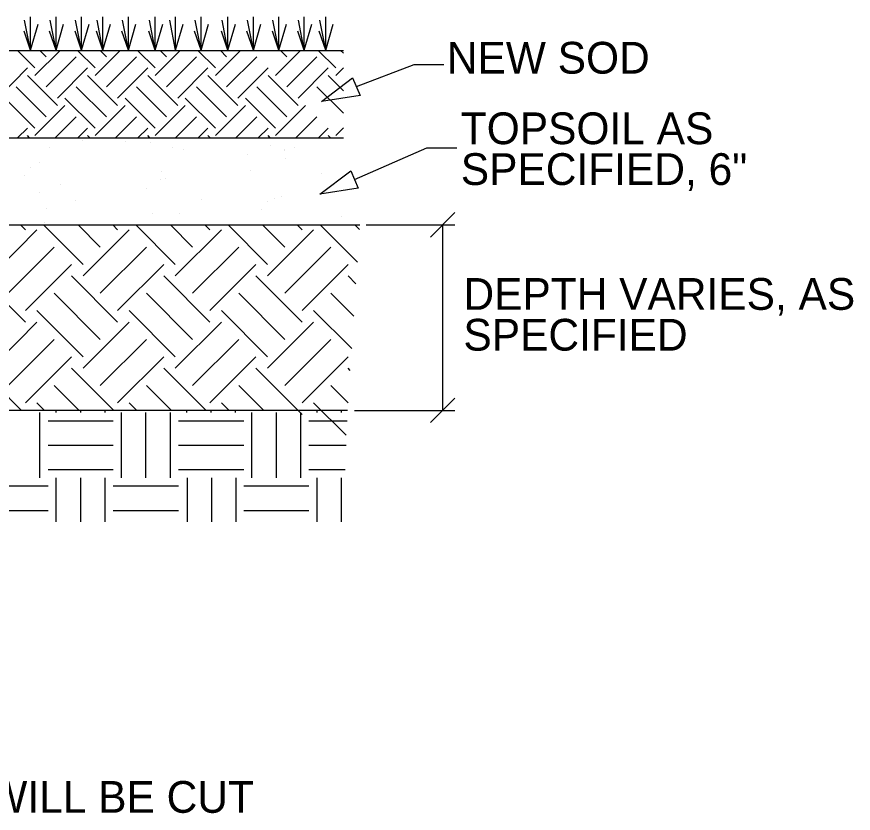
# Model space of a CAD drawing. Extents: x 10146.6 to 10186.7, y 9955.2 to 10001.8.
# Drawn here: x 10168.25 to 10186.68, y 9979.42 to 9996.98 of the extents above; entities that cross this region are included whole.
import ezdxf

# ---------------------------------------------------------------- set-up
doc = ezdxf.new("R2010")
doc.units = 0
for name, color, linetype in [('Default', 7, 'Continuous'), ('G-DETL-OTLN', 7, 'Continuous'), ('G-DETL-PATT', 7, 'Continuous'), ('G-DETL-TEXT', 7, 'Continuous')]:
    doc.layers.add(name, color=color, linetype=linetype)

# ---------------------------------------------------------------- blocks, each defined once
blk = doc.blocks.new('TERARR')
at = {"layer": 'Default'}
blk.add_lwpolyline([(-0.667, 0.167), (0, 0), (-0.667, -0.167)], close=True, dxfattribs=at)

msp = doc.modelspace()

# ---------------------------------------------------------------- linework, layer by layer
at = {"layer": 'Default'}
for p, q in [((10177.904, 9992.66), (10177.363, 9992.119)), ((10175.949, 9992.389), (10177.904, 9992.389)), ((10177.634, 9992.394), (10177.634, 9988.3)), ((10177.904, 9988.571), (10177.363, 9988.03)), ((10175.689, 9988.3), (10177.904, 9988.3))]:
    msp.add_line(p, q, dxfattribs=at)
at = {"layer": 'G-DETL-OTLN'}
for points in [[(10157.311, 9996.235), (10175.448, 9996.235)], [(10157.311, 9994.307), (10175.448, 9994.307)], [(10157.272, 9992.435), (10157.272, 9988.305), (10175.536, 9988.305)], [(10157.434, 9992.388), (10175.807, 9992.388)]]:
    msp.add_lwpolyline(points, dxfattribs=at)
at = {"layer": 'G-DETL-PATT'}
for p, q in [((10168.55, 9996.238), (10168.421, 9996.901)), ((10168.55, 9996.238), (10168.55, 9996.977)), ((10169.112, 9996.238), (10168.983, 9996.901)), ((10169.112, 9996.238), (10169.112, 9996.977)), ((10169.674, 9996.238), (10169.544, 9996.901)), ((10169.674, 9996.238), (10169.674, 9996.977)), ((10170.145, 9996.238), (10170.016, 9996.901)), ((10170.145, 9996.238), (10170.145, 9996.977)), ((10170.707, 9996.238), (10170.577, 9996.901)), ((10170.707, 9996.238), (10170.707, 9996.977)), ((10171.3, 9996.238), (10171.171, 9996.901)), ((10171.3, 9996.238), (10171.3, 9996.977)), ((10171.747, 9996.238), (10171.618, 9996.901)), ((10171.747, 9996.238), (10171.747, 9996.977)), ((10172.309, 9996.238), (10172.18, 9996.901)), ((10172.309, 9996.238), (10172.309, 9996.977)), ((10172.9, 9996.238), (10172.771, 9996.901)), ((10172.9, 9996.238), (10172.9, 9996.977)), ((10173.462, 9996.238), (10173.332, 9996.901)), ((10173.462, 9996.238), (10173.462, 9996.977)), ((10174.024, 9996.238), (10173.894, 9996.901)), ((10174.024, 9996.238), (10174.024, 9996.977)), ((10174.585, 9996.238), (10174.456, 9996.901)), ((10174.585, 9996.238), (10174.585, 9996.977)), ((10175.057, 9996.238), (10174.927, 9996.901)), ((10175.057, 9996.238), (10175.057, 9996.977)), ((10168.55, 9996.238), (10168.409, 9996.657)), ((10168.55, 9996.238), (10168.716, 9996.811)), ((10169.112, 9996.238), (10168.97, 9996.657)), ((10169.112, 9996.238), (10169.278, 9996.811)), ((10169.674, 9996.238), (10169.532, 9996.657)), ((10169.674, 9996.238), (10169.84, 9996.811)), ((10170.145, 9996.238), (10170.003, 9996.657)), ((10170.145, 9996.238), (10170.311, 9996.811)), ((10170.707, 9996.238), (10170.565, 9996.657)), ((10170.707, 9996.238), (10170.873, 9996.811)), ((10171.3, 9996.238), (10171.159, 9996.657)), ((10171.3, 9996.238), (10171.466, 9996.811)), ((10171.747, 9996.238), (10171.913, 9996.811)), ((10172.309, 9996.238), (10172.167, 9996.657)), ((10172.309, 9996.238), (10172.475, 9996.811)), ((10172.9, 9996.238), (10172.758, 9996.657)), ((10172.9, 9996.238), (10173.066, 9996.811)), ((10173.462, 9996.238), (10173.32, 9996.657)), ((10173.462, 9996.238), (10173.628, 9996.811)), ((10174.024, 9996.238), (10173.882, 9996.657)), ((10174.024, 9996.238), (10174.19, 9996.811)), ((10174.585, 9996.238), (10174.444, 9996.657)), ((10174.585, 9996.238), (10174.751, 9996.811)), ((10175.057, 9996.238), (10174.915, 9996.657)), ((10175.057, 9996.238), (10175.223, 9996.811)), ((10168.647, 9995.848), (10168.26, 9996.235)), ((10168.647, 9995.682), (10169.201, 9996.235)), ((10168.896, 9996.096), (10168.757, 9996.235)), ((10168.896, 9995.433), (10169.559, 9996.096)), ((10169.973, 9995.848), (10169.586, 9996.235)), ((10169.973, 9995.682), (10170.526, 9996.235)), ((10170.222, 9996.096), (10170.083, 9996.235)), ((10170.222, 9995.433), (10170.885, 9996.096)), ((10171.299, 9995.848), (10170.911, 9996.235)), ((10171.299, 9995.682), (10171.852, 9996.235)), ((10171.548, 9996.096), (10171.409, 9996.235)), ((10171.548, 9995.433), (10172.211, 9996.096)), ((10172.625, 9995.848), (10172.237, 9996.235)), ((10172.625, 9995.682), (10173.178, 9996.235)), ((10172.873, 9996.096), (10172.734, 9996.235)), ((10172.873, 9995.433), (10173.536, 9996.096)), ((10173.951, 9995.682), (10174.504, 9996.235)), ((10174.199, 9996.096), (10174.06, 9996.235)), ((10174.199, 9995.433), (10174.862, 9996.096)), ((10175.276, 9995.848), (10174.889, 9996.235)), ((10175.448, 9996.173), (10175.386, 9996.235)), ((10167.819, 9995.185), (10168.482, 9995.848)), ((10169.145, 9995.185), (10169.807, 9995.848)), ((10170.47, 9995.185), (10171.133, 9995.848)), ((10171.796, 9995.185), (10172.459, 9995.848)), ((10173.122, 9995.185), (10173.785, 9995.848)), ((10174.448, 9995.185), (10175.111, 9995.848)), ((10175.276, 9995.682), (10175.448, 9995.854)), ((10169.145, 9995.019), (10168.482, 9995.682)), ((10170.47, 9995.019), (10169.807, 9995.682)), ((10171.796, 9995.019), (10171.133, 9995.682)), ((10173.122, 9995.019), (10172.459, 9995.682)), ((10174.448, 9995.019), (10173.785, 9995.682)), ((10175.448, 9995.345), (10175.111, 9995.682)), ((10168.896, 9994.771), (10168.233, 9995.433)), ((10170.222, 9994.771), (10169.559, 9995.433)), ((10171.548, 9994.771), (10170.885, 9995.433)), ((10172.873, 9994.771), (10172.211, 9995.433)), ((10174.199, 9994.771), (10173.536, 9995.433)), ((10175.448, 9994.848), (10174.862, 9995.433)), ((10168.647, 9994.522), (10167.984, 9995.185)), ((10169.973, 9994.522), (10169.31, 9995.185)), ((10171.299, 9994.522), (10170.636, 9995.185)), ((10172.625, 9994.522), (10171.962, 9995.185)), ((10173.951, 9994.522), (10173.288, 9995.185)), ((10168.647, 9994.356), (10169.31, 9995.019)), ((10169.973, 9994.356), (10170.636, 9995.019)), ((10171.299, 9994.356), (10171.962, 9995.019)), ((10172.625, 9994.356), (10173.288, 9995.019)), ((10173.951, 9994.356), (10174.614, 9995.019)), ((10169.095, 9994.307), (10169.559, 9994.771)), ((10170.421, 9994.307), (10170.885, 9994.771)), ((10171.747, 9994.307), (10172.211, 9994.771)), ((10173.072, 9994.307), (10173.536, 9994.771)), ((10174.398, 9994.307), (10174.862, 9994.771)), ((10168.266, 9994.307), (10168.482, 9994.522)), ((10169.592, 9994.307), (10169.807, 9994.522)), ((10170.918, 9994.307), (10171.133, 9994.522)), ((10172.244, 9994.307), (10172.459, 9994.522)), ((10173.57, 9994.307), (10173.785, 9994.522)), ((10174.895, 9994.307), (10175.111, 9994.522)), ((10175.276, 9994.356), (10175.448, 9994.528)), ((10168.531, 9994.307), (10168.482, 9994.356)), ((10169.857, 9994.307), (10169.807, 9994.356)), ((10171.183, 9994.307), (10171.133, 9994.356)), ((10172.509, 9994.307), (10172.459, 9994.356)), ((10173.835, 9994.307), (10173.785, 9994.356)), ((10175.16, 9994.307), (10175.111, 9994.356)), ((10168.975, 9994.096), (10168.975, 9994.096)), ((10169.688, 9994.243), (10169.688, 9994.243)), ((10170.639, 9994.22), (10170.639, 9994.22)), ((10171.191, 9994.209), (10171.191, 9994.209)), ((10171.675, 9994.096), (10171.675, 9994.096)), ((10173.83, 9994.145), (10173.83, 9994.145)), ((10174.375, 9994.096), (10174.375, 9994.096)), ((10171.929, 9994.047), (10171.929, 9994.047)), ((10173.324, 9993.938), (10173.324, 9993.938)), ((10174.138, 9994.056), (10174.138, 9994.056)), ((10174.154, 9994.027), (10174.154, 9994.027)), ((10168.739, 9993.775), (10168.739, 9993.775)), ((10174.171, 9993.851), (10174.171, 9993.851)), ((10168.55, 9993.648), (10168.55, 9993.648)), ((10171.447, 9993.568), (10171.447, 9993.568)), ((10173.403, 9993.584), (10173.403, 9993.584)), ((10174.961, 9993.516), (10174.961, 9993.516)), ((10168.411, 9993.475), (10168.411, 9993.475)), ((10171.413, 9993.399), (10171.413, 9993.399)), ((10171.518, 9993.403), (10171.518, 9993.403)), ((10169.21, 9993.289), (10169.21, 9993.289)), ((10171.096, 9993.193), (10171.096, 9993.193)), ((10168.739, 9993.108), (10168.739, 9993.108)), ((10173.918, 9992.978), (10173.918, 9992.978)), ((10174.086, 9993.023), (10174.086, 9993.023)), ((10169.535, 9992.931), (10169.535, 9992.931)), ((10172.32, 9992.955), (10172.32, 9992.955)), ((10173.782, 9992.91), (10173.782, 9992.91)), ((10168.899, 9992.75), (10168.899, 9992.75)), ((10171.238, 9992.649), (10171.238, 9992.649)), ((10171.83, 9992.636), (10171.83, 9992.636)), ((10173.631, 9992.733), (10173.631, 9992.733)), ((10168.869, 9992.447), (10168.869, 9992.447)), ((10175.408, 9992.563), (10175.408, 9992.563)), ((10167.675, 9991.263), (10168.692, 9992.279)), ((10168.437, 9992.279), (10168.328, 9992.388)), ((10169.708, 9991.517), (10168.837, 9992.388)), ((10170.089, 9991.898), (10169.599, 9992.388)), ((10169.679, 9992.394), (10169.679, 9992.394)), ((10169.708, 9991.263), (10170.724, 9992.279)), ((10170.47, 9992.279), (10170.361, 9992.388)), ((10171.741, 9991.517), (10170.87, 9992.388)), ((10172.122, 9991.898), (10171.632, 9992.388)), ((10171.741, 9991.263), (10172.757, 9992.279)), ((10172.503, 9992.279), (10172.394, 9992.388)), ((10173.774, 9991.517), (10172.903, 9992.388)), ((10174.155, 9991.898), (10173.665, 9992.388)), ((10173.774, 9991.263), (10174.79, 9992.279)), ((10174.536, 9992.279), (10174.427, 9992.388)), ((10175.754, 9991.57), (10174.936, 9992.388)), ((10175.8, 9992.286), (10175.698, 9992.388)), ((10168.056, 9990.881), (10169.073, 9991.898)), ((10170.089, 9990.881), (10171.106, 9991.898)), ((10172.122, 9990.881), (10173.139, 9991.898)), ((10174.155, 9990.881), (10175.172, 9991.898)), ((10168.437, 9990.5), (10169.454, 9991.517)), ((10170.47, 9990.5), (10171.487, 9991.517)), ((10172.503, 9990.5), (10173.52, 9991.517)), ((10174.536, 9990.5), (10175.553, 9991.517)), ((10168.437, 9990.246), (10167.421, 9991.263)), ((10170.47, 9990.246), (10169.454, 9991.263)), ((10172.503, 9990.246), (10171.487, 9991.263)), ((10174.536, 9990.246), (10173.52, 9991.263)), ((10175.723, 9991.093), (10175.553, 9991.263)), ((10170.089, 9989.865), (10169.073, 9990.881)), ((10172.122, 9989.865), (10171.106, 9990.881)), ((10174.155, 9989.865), (10173.139, 9990.881)), ((10175.676, 9990.377), (10175.172, 9990.881)), ((10169.708, 9989.484), (10168.692, 9990.5)), ((10171.741, 9989.484), (10170.724, 9990.5)), ((10173.774, 9989.484), (10172.757, 9990.5)), ((10175.63, 9989.661), (10174.79, 9990.5)), ((10167.675, 9989.23), (10168.692, 9990.246)), ((10169.708, 9989.23), (10170.724, 9990.246)), ((10171.741, 9989.23), (10172.757, 9990.246)), ((10173.774, 9989.23), (10174.79, 9990.246)), ((10168.056, 9988.848), (10169.073, 9989.865)), ((10170.089, 9988.848), (10171.106, 9989.865)), ((10172.122, 9988.848), (10173.139, 9989.865)), ((10174.155, 9988.848), (10175.172, 9989.865)), ((10168.437, 9988.467), (10169.454, 9989.484)), ((10170.47, 9988.467), (10171.487, 9989.484)), ((10172.503, 9988.467), (10173.52, 9989.484)), ((10174.536, 9988.467), (10175.553, 9989.484)), ((10168.346, 9988.305), (10167.421, 9989.23)), ((10170.378, 9988.305), (10169.454, 9989.23)), ((10172.411, 9988.305), (10171.487, 9989.23)), ((10174.536, 9988.213), (10173.52, 9989.23)), ((10175.599, 9989.183), (10175.553, 9989.23)), ((10169.616, 9988.305), (10169.073, 9988.848)), ((10171.649, 9988.305), (10171.106, 9988.848)), ((10173.682, 9988.305), (10173.139, 9988.848)), ((10175.552, 9988.468), (10175.172, 9988.848)), ((10168.854, 9988.305), (10168.692, 9988.467)), ((10170.887, 9988.305), (10170.724, 9988.467)), ((10172.92, 9988.305), (10172.757, 9988.467)), ((10175.506, 9987.752), (10174.79, 9988.467)), ((10168.758, 9986.815), (10168.758, 9988.253)), ((10169.118, 9988.253), (10169.118, 9988.305)), ((10169.657, 9988.253), (10169.657, 9988.305)), ((10170.196, 9988.253), (10170.196, 9988.305)), ((10170.555, 9986.815), (10170.555, 9988.253)), ((10171.094, 9986.815), (10171.094, 9988.253)), ((10171.633, 9986.815), (10171.633, 9988.253)), ((10171.993, 9988.253), (10171.993, 9988.305)), ((10172.532, 9988.253), (10172.532, 9988.305)), ((10173.071, 9988.253), (10173.071, 9988.305)), ((10173.43, 9986.815), (10173.43, 9988.253)), ((10173.969, 9986.815), (10173.969, 9988.253)), ((10174.508, 9986.815), (10174.508, 9988.253)), ((10174.868, 9988.253), (10174.868, 9988.305)), ((10175.407, 9988.253), (10175.407, 9988.305)), ((10168.938, 9988.073), (10170.375, 9988.073)), ((10171.813, 9988.073), (10173.25, 9988.073)), ((10174.688, 9988.073), (10175.528, 9988.073)), ((10168.938, 9987.534), (10170.375, 9987.534)), ((10171.813, 9987.534), (10173.25, 9987.534)), ((10174.688, 9987.534), (10175.508, 9987.534)), ((10168.938, 9986.995), (10170.375, 9986.995)), ((10171.813, 9986.995), (10173.25, 9986.995)), ((10174.688, 9986.995), (10175.489, 9986.995)), ((10169.118, 9985.843), (10169.118, 9986.815)), ((10169.657, 9985.843), (10169.657, 9986.815)), ((10170.196, 9985.843), (10170.196, 9986.815)), ((10172.008, 9985.843), (10172.008, 9986.815)), ((10172.547, 9985.843), (10172.547, 9986.815)), ((10173.086, 9985.843), (10173.086, 9986.815)), ((10174.868, 9985.843), (10174.868, 9986.815)), ((10175.407, 9985.843), (10175.407, 9986.815)), ((10167.5, 9986.635), (10168.938, 9986.635)), ((10170.375, 9986.635), (10171.813, 9986.635)), ((10173.25, 9986.635), (10174.688, 9986.635)), ((10167.5, 9986.096), (10168.938, 9986.096)), ((10170.375, 9986.096), (10171.813, 9986.096)), ((10173.25, 9986.096), (10174.688, 9986.096))]:
    msp.add_line(p, q, dxfattribs=at)
for points in [[(10175.732, 9995.436), (10177.005, 9995.925), (10177.661, 9995.925)], [(10175.691, 9993.39), (10177.288, 9994.089), (10177.945, 9994.089)]]:
    msp.add_lwpolyline(points, dxfattribs=at)

# ---------------------------------------------------------------- block references
at = {"layer": 'G-DETL-PATT', "xscale": 1.25, "yscale": 1.2500000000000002, "rotation": -157.00827200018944}
for p in [(10174.964, 9995.111), (10174.924, 9993.064)]:
    msp.add_blockref('TERARR', p, dxfattribs=at)

# ---------------------------------------------------------------- texts
at = {"layer": 'G-DETL-TEXT'}
for s, p in [('NEW SOD', (10177.726, 9995.723)), ('TOPSOIL AS ', (10178.034, 9994.168)), ('SPECIFIED, 6"', (10178.034, 9993.269)), ('DEPTH VARIES, AS ', (10178.092, 9990.517)), ('SPECIFIED', (10178.092, 9989.618)), ('EDGES OF NEW SOD WILL BE CUT ', (10157.767, 9979.431))]:
    msp.add_text(s, height=0.7, dxfattribs=at).set_placement(p)

doc.saveas('drawing.dxf')
